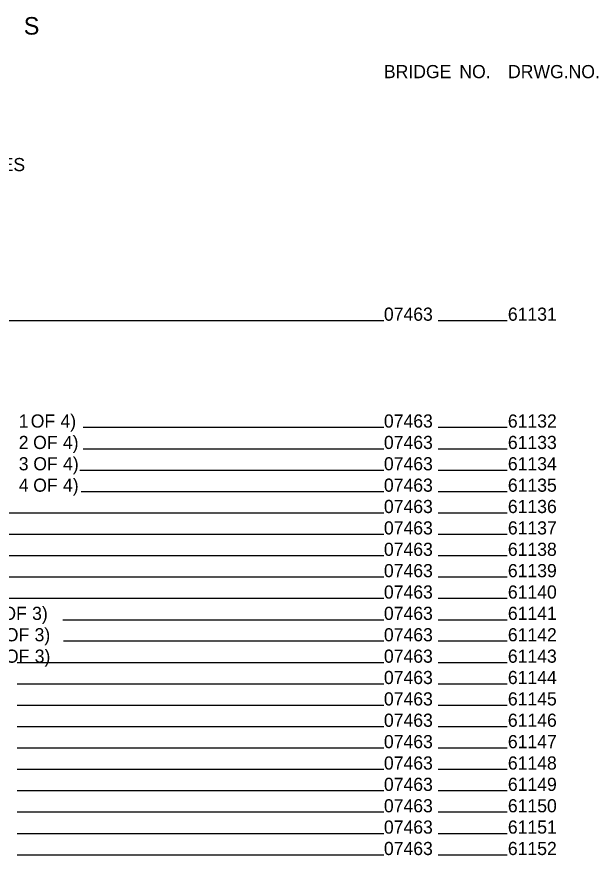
# Model space of a CAD drawing. Extents: x 2 to 32.9, y 0.7 to 21.4.
# Drawn here: x 9.25 to 16.2, y 11.25 to 21.28 of the extents above; entities that cross this region are included whole.
import ezdxf

# ---------------------------------------------------------------- set-up
doc = ezdxf.new("R2010")
doc.units = 0
doc.layers.add('Default', color=7, linetype='Continuous')

msp = doc.modelspace()

# ---------------------------------------------------------------- linework, layer by layer
at = {"layer": 'Default'}
for p, q in [((7.594, 17.649), (13.635, 17.649)), ((14.286, 17.649), (15.114, 17.649)), ((10.038, 16.371), (13.635, 16.371)), ((14.286, 16.371), (15.114, 16.371)), ((10.038, 16.115), (13.635, 16.115)), ((14.286, 16.115), (15.114, 16.115)), ((10, 15.859), (13.635, 15.859)), ((14.286, 15.859), (15.114, 15.859)), ((10.016, 15.604), (13.635, 15.604)), ((14.286, 15.604), (15.114, 15.604)), ((7.142, 15.348), (13.635, 15.348)), ((14.286, 15.348), (15.114, 15.348)), ((7.936, 15.093), (13.635, 15.093)), ((14.286, 15.093), (15.114, 15.093)), ((7.973, 14.837), (13.635, 14.837)), ((14.286, 14.837), (15.114, 14.837)), ((7.955, 14.581), (13.635, 14.581)), ((14.286, 14.581), (15.114, 14.581)), ((7.961, 14.326), (13.635, 14.326)), ((14.286, 14.326), (15.114, 14.326)), ((9.795, 14.07), (13.635, 14.07)), ((14.286, 14.07), (15.114, 14.07)), ((9.805, 13.815), (13.635, 13.815)), ((14.286, 13.815), (15.114, 13.815)), ((9.252, 13.559), (13.635, 13.559)), ((14.286, 13.559), (15.114, 13.559)), ((9.252, 13.303), (13.635, 13.303)), ((14.286, 13.303), (15.114, 13.303)), ((9.252, 13.048), (13.635, 13.048)), ((14.286, 13.048), (15.114, 13.048)), ((9.252, 12.792), (13.635, 12.792)), ((14.286, 12.792), (15.114, 12.792)), ((9.252, 12.537), (13.635, 12.537)), ((14.286, 12.537), (15.114, 12.537)), ((9.252, 12.281), (13.635, 12.281)), ((14.286, 12.281), (15.114, 12.281)), ((9.252, 12.026), (13.635, 12.026)), ((14.286, 12.026), (15.114, 12.026)), ((9.252, 11.77), (13.635, 11.77)), ((14.286, 11.77), (15.114, 11.77)), ((9.252, 11.514), (13.635, 11.514)), ((14.286, 11.514), (15.114, 11.514)), ((9.252, 11.259), (13.635, 11.259)), ((14.286, 11.259), (15.114, 11.259))]:
    msp.add_line(p, q, dxfattribs=at)

# ---------------------------------------------------------------- texts
for s, height, p in [(' S', 0.2097, (9.251, 21.067)), (' S', 0.2097, (9.251, 21.067)), ('BRIDGE', 0.1573, (13.638, 20.546)), ('BRIDGE', 0.1573, (13.638, 20.546)), (' NO.', 0.1573, (14.482, 20.546)), (' NO.', 0.1573, (14.482, 20.546)), ('DRWG.NO.', 0.1573, (15.123, 20.546)), ('DRWG.NO.', 0.1573, (15.123, 20.546)), (' NOTES', 0.1573, (8.562, 19.434)), (' NOTES', 0.1573, (8.562, 19.434)), ('07463', 0.1573, (13.638, 17.645)), ('07463', 0.1573, (13.638, 17.645)), ('61131', 0.1573, (15.121, 17.645)), ('61131', 0.1573, (15.121, 17.645)), (' 1', 0.1573, (9.211, 16.367)), (' 1', 0.1573, (9.211, 16.367)), (' OF', 0.1573, (9.354, 16.367)), (' OF', 0.1573, (9.354, 16.367)), (' 4)', 0.1573, (9.71, 16.367)), (' 4)', 0.1573, (9.71, 16.367)), ('07463', 0.1573, (13.638, 16.367)), ('07463', 0.1573, (13.638, 16.367)), ('61132', 0.1573, (15.121, 16.367)), ('61132', 0.1573, (15.121, 16.367)), (' 2', 0.1573, (9.211, 16.111)), (' 2', 0.1573, (9.211, 16.111)), (' OF', 0.1573, (9.383, 16.111)), (' OF', 0.1573, (9.383, 16.111)), (' 4)', 0.1573, (9.739, 16.111)), (' 4)', 0.1573, (9.739, 16.111)), ('07463', 0.1573, (13.638, 16.111)), ('07463', 0.1573, (13.638, 16.111)), ('61133', 0.1573, (15.121, 16.111)), ('61133', 0.1573, (15.121, 16.111)), (' 3', 0.1573, (9.211, 15.856)), (' 3', 0.1573, (9.211, 15.856)), (' OF', 0.1573, (9.385, 15.856)), (' OF', 0.1573, (9.385, 15.856)), (' 4)', 0.1573, (9.741, 15.856)), (' 4)', 0.1573, (9.741, 15.856)), ('07463', 0.1573, (13.638, 15.856)), ('07463', 0.1573, (13.638, 15.856)), ('61134', 0.1573, (15.121, 15.856)), ('61134', 0.1573, (15.121, 15.856)), (' 4', 0.1573, (9.211, 15.6)), (' 4', 0.1573, (9.211, 15.6)), (' OF', 0.1573, (9.384, 15.6)), (' OF', 0.1573, (9.384, 15.6)), (' 4)', 0.1573, (9.74, 15.6)), (' 4)', 0.1573, (9.74, 15.6)), ('07463', 0.1573, (13.638, 15.6)), ('07463', 0.1573, (13.638, 15.6)), ('61135', 0.1573, (15.121, 15.6)), ('61135', 0.1573, (15.121, 15.6)), ('07463', 0.1573, (13.638, 15.345)), ('07463', 0.1573, (13.638, 15.345)), ('61136', 0.1573, (15.121, 15.345)), ('61136', 0.1573, (15.121, 15.345)), ('07463', 0.1573, (13.638, 15.089)), ('07463', 0.1573, (13.638, 15.089)), ('61137', 0.1573, (15.121, 15.089)), ('61137', 0.1573, (15.121, 15.089)), ('07463', 0.1573, (13.638, 14.833)), ('07463', 0.1573, (13.638, 14.833)), ('61138', 0.1573, (15.121, 14.833)), ('61138', 0.1573, (15.121, 14.833)), ('07463', 0.1573, (13.638, 14.578)), ('07463', 0.1573, (13.638, 14.578)), ('61139', 0.1573, (15.121, 14.578)), ('61139', 0.1573, (15.121, 14.578)), ('07463', 0.1573, (13.638, 14.322)), ('07463', 0.1573, (13.638, 14.322)), ('61140', 0.1573, (15.121, 14.322)), ('61140', 0.1573, (15.121, 14.322)), (' OF', 0.1573, (9.015, 14.067)), (' OF', 0.1573, (9.015, 14.067)), (' 3)', 0.1573, (9.371, 14.067)), (' 3)', 0.1573, (9.371, 14.067)), ('07463', 0.1573, (13.638, 14.067)), ('07463', 0.1573, (13.638, 14.067)), ('61141', 0.1573, (15.121, 14.067)), ('61141', 0.1573, (15.121, 14.067)), (' OF', 0.1573, (9.044, 13.811)), (' OF', 0.1573, (9.044, 13.811)), (' 3)', 0.1573, (9.4, 13.811)), (' 3)', 0.1573, (9.4, 13.811)), ('07463', 0.1573, (13.638, 13.811)), ('07463', 0.1573, (13.638, 13.811)), ('61142', 0.1573, (15.121, 13.811)), ('61142', 0.1573, (15.121, 13.811)), (' OF', 0.1573, (9.046, 13.555)), (' OF', 0.1573, (9.046, 13.555)), (' 3)', 0.1573, (9.402, 13.555)), (' 3)', 0.1573, (9.402, 13.555)), ('07463', 0.1573, (13.638, 13.555)), ('07463', 0.1573, (13.638, 13.555)), ('61143', 0.1573, (15.121, 13.555)), ('61143', 0.1573, (15.121, 13.555)), ('07463', 0.1573, (13.638, 13.3)), ('07463', 0.1573, (13.638, 13.3)), ('61144', 0.1573, (15.121, 13.3)), ('61144', 0.1573, (15.121, 13.3)), ('07463', 0.1573, (13.638, 13.044)), ('07463', 0.1573, (13.638, 13.044)), ('61145', 0.1573, (15.121, 13.044)), ('61145', 0.1573, (15.121, 13.044)), ('07463', 0.1573, (13.638, 12.789)), ('07463', 0.1573, (13.638, 12.789)), ('61146', 0.1573, (15.121, 12.789)), ('61146', 0.1573, (15.121, 12.789)), ('07463', 0.1573, (13.638, 12.533)), ('07463', 0.1573, (13.638, 12.533)), ('61147', 0.1573, (15.121, 12.533)), ('61147', 0.1573, (15.121, 12.533)), ('07463', 0.1573, (13.638, 12.277)), ('07463', 0.1573, (13.638, 12.277)), ('61148', 0.1573, (15.121, 12.277)), ('61148', 0.1573, (15.121, 12.277)), ('07463', 0.1573, (13.638, 12.022)), ('07463', 0.1573, (13.638, 12.022)), ('61149', 0.1573, (15.121, 12.022)), ('61149', 0.1573, (15.121, 12.022)), ('07463', 0.1573, (13.638, 11.766)), ('07463', 0.1573, (13.638, 11.766)), ('61150', 0.1573, (15.121, 11.766)), ('61150', 0.1573, (15.121, 11.766)), ('07463', 0.1573, (13.638, 11.511)), ('07463', 0.1573, (13.638, 11.511)), ('61151', 0.1573, (15.121, 11.511)), ('61151', 0.1573, (15.121, 11.511)), ('07463', 0.1573, (13.638, 11.255)), ('07463', 0.1573, (13.638, 11.255)), ('61152', 0.1573, (15.121, 11.255)), ('61152', 0.1573, (15.121, 11.255))]:
    msp.add_text(s, height=height, dxfattribs=at).set_placement(p)

doc.saveas('drawing.dxf')
